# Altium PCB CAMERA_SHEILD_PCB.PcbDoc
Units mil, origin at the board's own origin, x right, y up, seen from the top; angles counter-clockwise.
Board outline 1750 x 2100 mil, 2 copper layers (Top Layer, Bottom Layer); 31 components, 29 nets, 109 pads, 36 vias.
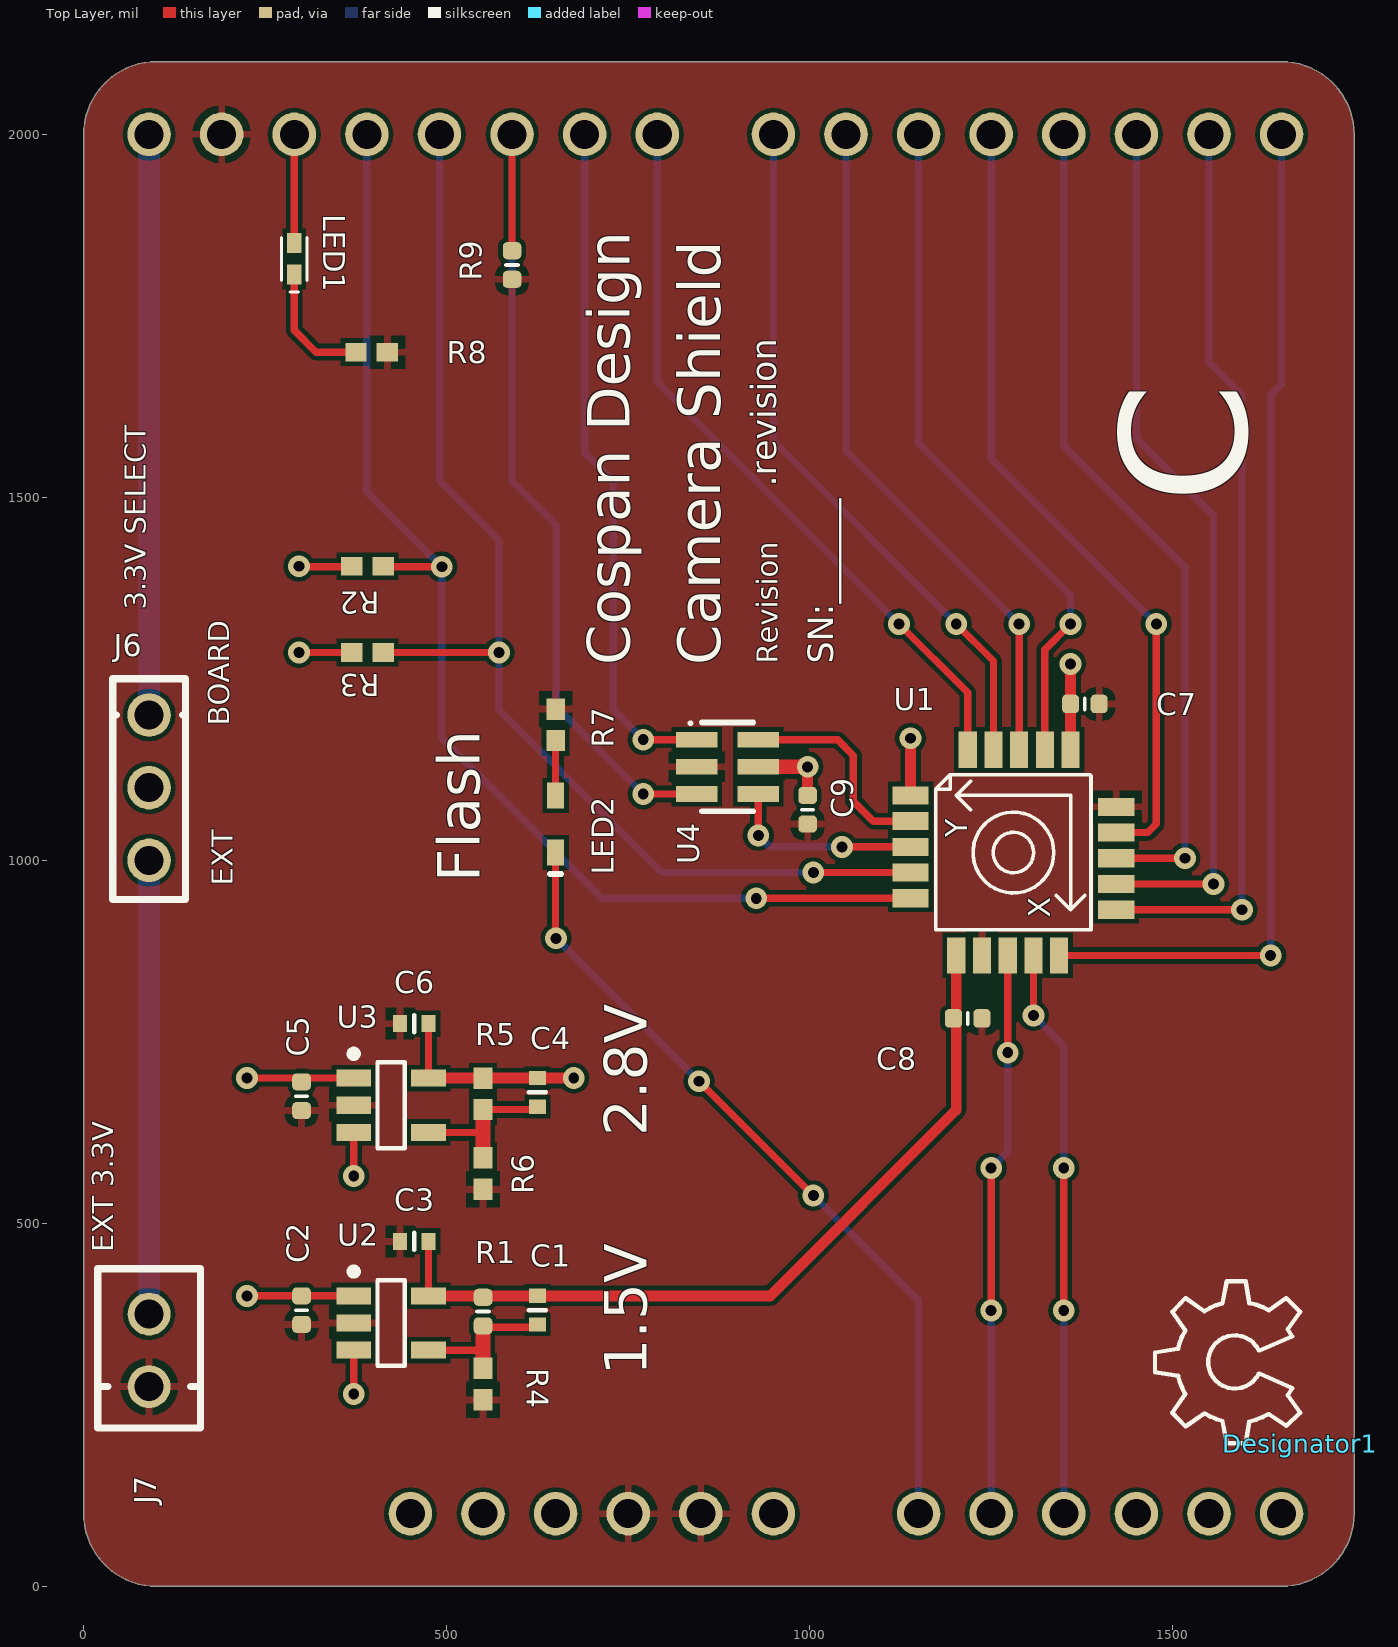
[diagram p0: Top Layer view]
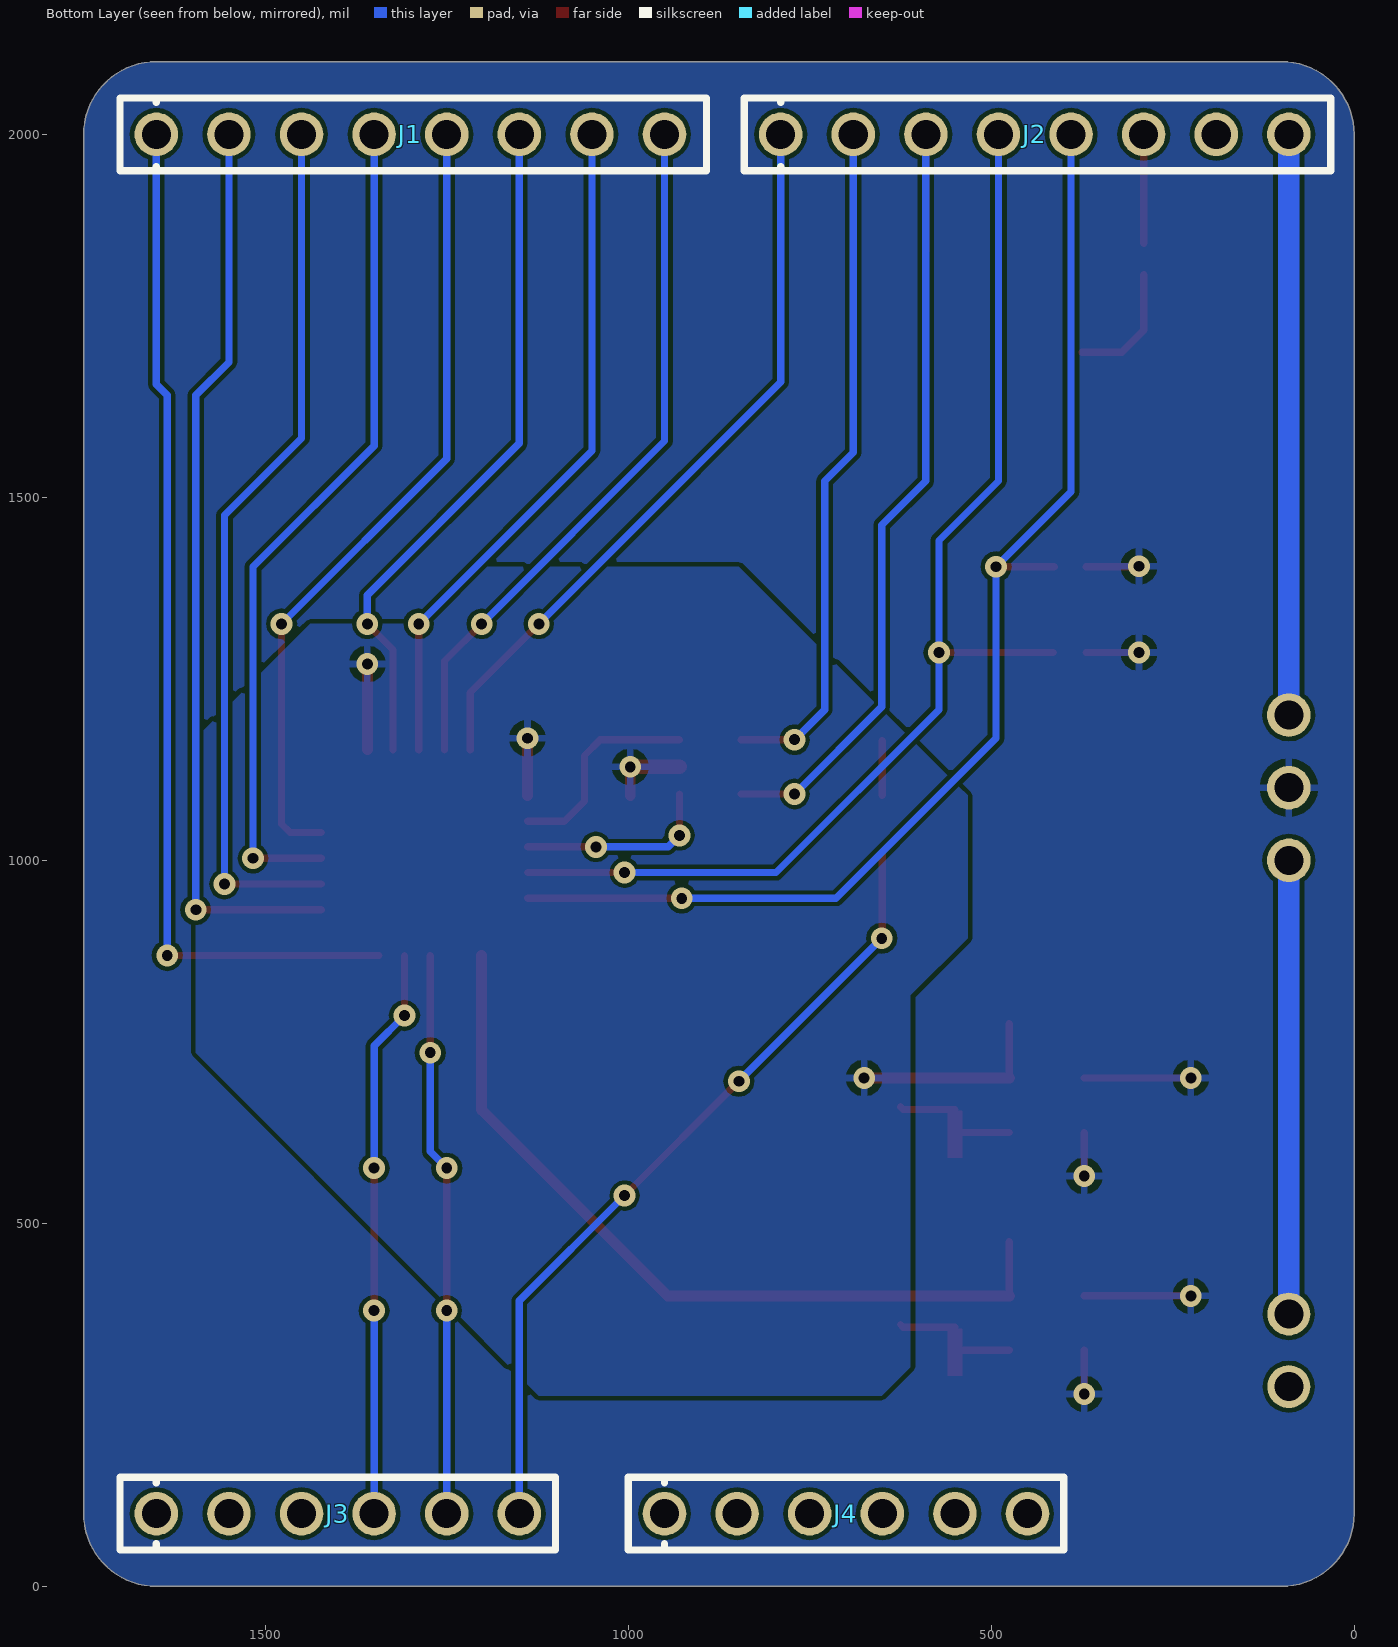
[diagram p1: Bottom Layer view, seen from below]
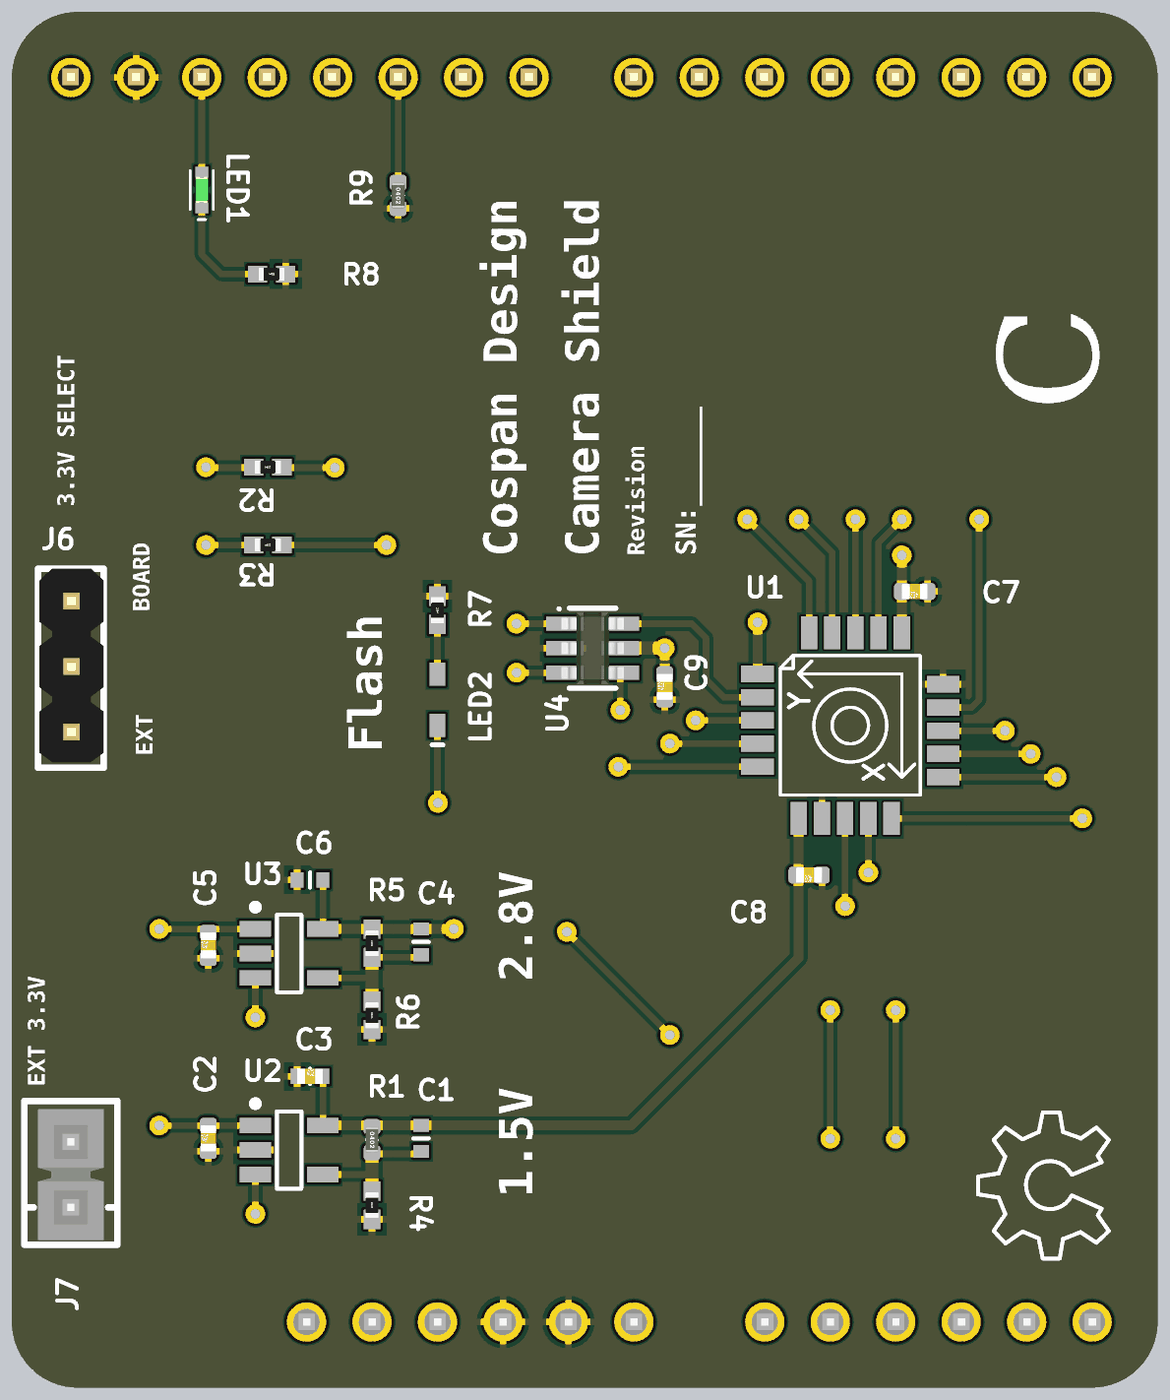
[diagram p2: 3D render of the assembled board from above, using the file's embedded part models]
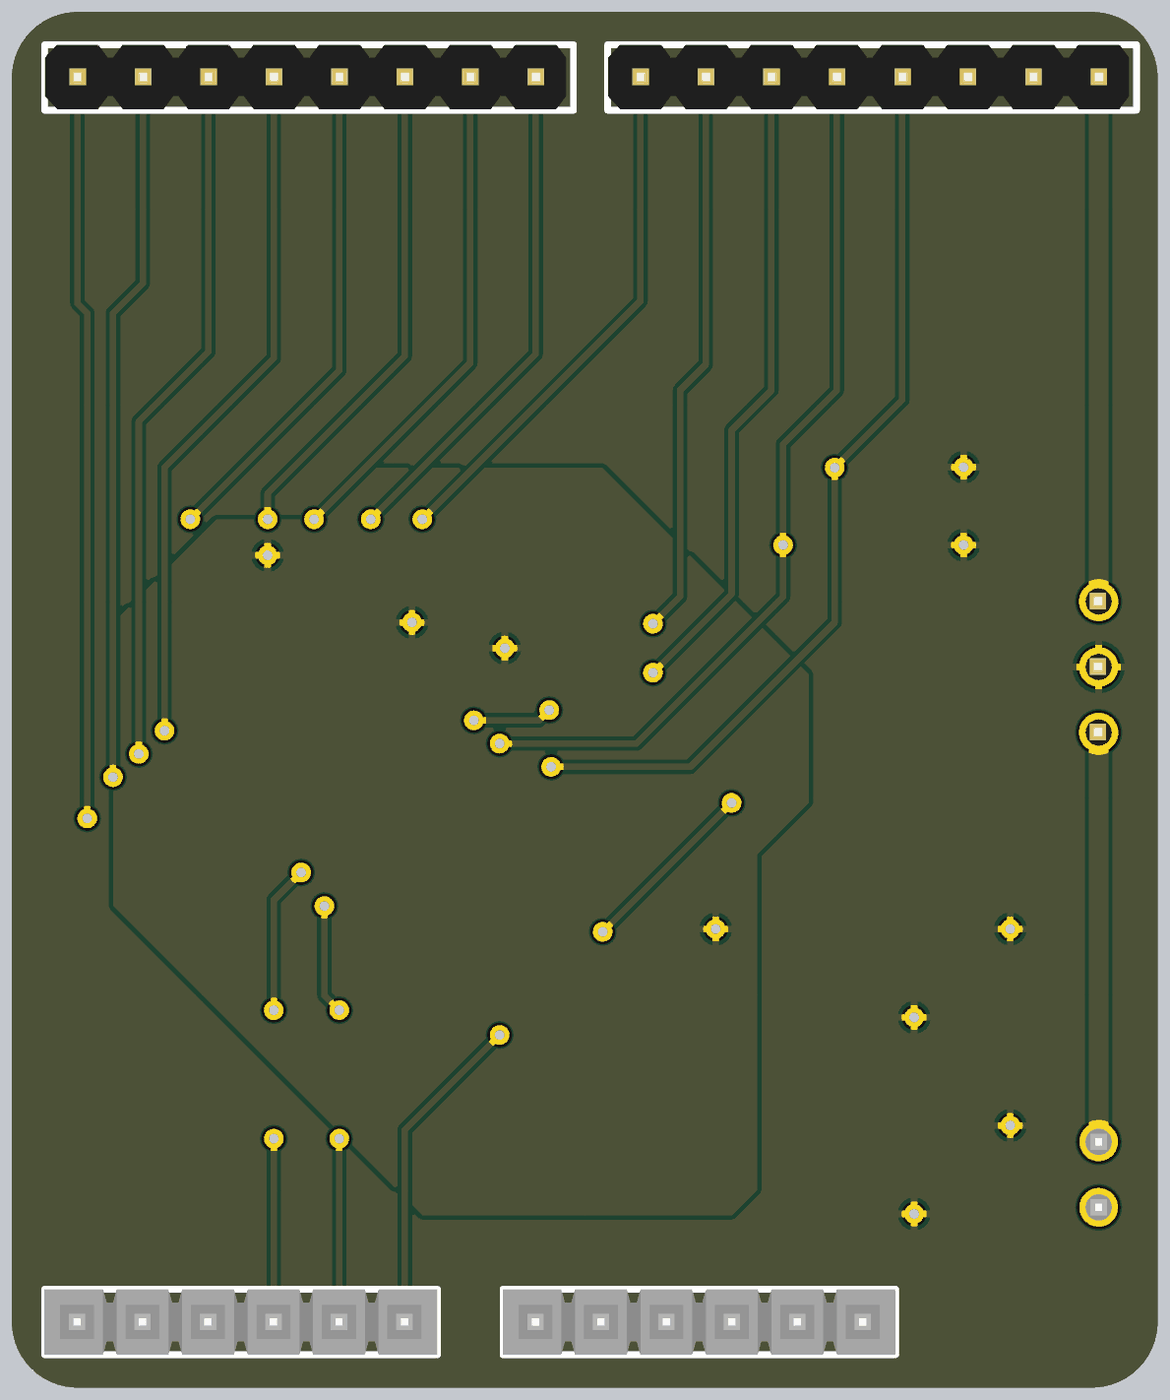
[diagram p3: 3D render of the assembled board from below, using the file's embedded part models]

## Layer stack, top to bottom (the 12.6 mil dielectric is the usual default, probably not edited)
Top Layer: signal copper 1.4
Dielectric: dielectric 12.6, FR-4, Dk 4.8
Bottom Layer: signal copper 1.4

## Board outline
0,100 0,2000 cw(c100,2000) 100,2100 1650,2100 cw(c1650,2000) 1750,2000 1750,100 cw(c1650,100) 1650,0 100,0 cw(c100,100)

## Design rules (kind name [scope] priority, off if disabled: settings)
Clearance [All] p1: gap=6
MinimumSolderMaskSliver [All] p1: minsoldermaskwidth=3
PolygonConnect [All] p1: connectstyle=Relief reliefconductorwidth=10 reliefentries=4 polygonreliefangle="90 Angle" airgapwidth=10
RoutingVias [All] p1: holewidth=15 width=30 viastyle="Through Hole" minholewidth=15 minwidth=30 maxholewidth=28 maxwidth=50
SilkToSilkClearance [All] p1: silktosilkclearance=5
SilkToSolderMaskClearance SilkscreenOverComponentPads [IsPad] p1: minsilkscreentomaskgap=3 clearancetoexposedcopper=TRUE
SolderMaskExpansion [All] p1: expansion=4
Width [All] p1: maxlimit=50 minlimit=6 preferedwidth=6
25 further rules are at their usual default settings.

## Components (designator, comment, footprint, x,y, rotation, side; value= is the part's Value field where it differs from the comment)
C1 "1000pF" C_ERA-0402 625,380.31 r90 top
C2 "0.1uF" C_0402 300,380.31 r90 top
C3 "2.2uF" C_ERA-0402 455.31,475 r0 top
C4 "1000pF" C_ERA-0402 625,680.31 r90 top
C5 "0.1uF" C_0402 300,675 r90 top
C6 "2.2uF" C_ERA-0402 455.31,775 r0 top
C7 "0.1uF" C_0402 1379.06,1215.35 r180 top
C8 "0.1uF" C_0402 1217.64,782.28 r180 top
C9 "0.1uF" C_0402 997.17,1069.69 r90 top
Designator1 "Comment" OSHW_6X200_NOTEXT 1675.59,196.97 r90 top (schematic designator U$5)
J1 "J_HDR1X8_THRHOLE_VERT" HDR_1X8 1650,2000 r180 bottom locked
J2 "J_HDR1X8_THRHOLE_VERT" HDR_1X8 790,2000 r180 bottom locked
J3 "J_HDR1X6_THRHOLE_VERT" HDR_1X6 1650,100 r180 bottom locked
J4 "J_HDR1X6_THRHOLE_VERT" HDR_1X6 950,100 r180 bottom locked
J6 "J_HDR1X3_JUMPER_SELECT" HDR_1X3 90,1200 r270 top
J7 "J_HDR1X2_JUMPER" HDR_1X2 90,275 r90 top
LED1 "LED_GRN_0402" DIOM1005X07L_GREEN 290,1828.35 r90 top
LED2 "LED_WHITE_0603" DIOM0603 650,1050 r270 top
R1 "R_0402_7.87K" R_0402 550,378.35 r270 top
R2 "2.2k Ohms" ERA-0402 390.87,1405.04 r0 top
R3 "2.2k Ohms" ERA-0402 390.87,1286.22 r0 top
R4 "R_0402_10.0K" ERA-0402 550,278.35 r270 top
R5 "R_0402_13.7K" ERA-0402 550,678.35 r270 top
R6 "R_0402_10.0K" ERA-0402 550,568.35 r270 top
R7 "R_0402_22.0" ERA-0402 650,1186.65 r90 top
R8 "1.0k Ohms" ERA-0402 396.65,1700 r0 top
R9 "R_0402_10.0K" R_0402 590,1820 r270 top
U1 "640X480 Camera" TCM8230MD 1280.63,1010.63 r90 top
U2 "VREG" SOT95P280X90-5N 423.43,362.6 r0 top
U3 "VREG" SOT95P280X90-5N 423.43,662.6 r0 top
U4 "2 X BUFFER" SOT23-6 886.93,1128.74 r270 top

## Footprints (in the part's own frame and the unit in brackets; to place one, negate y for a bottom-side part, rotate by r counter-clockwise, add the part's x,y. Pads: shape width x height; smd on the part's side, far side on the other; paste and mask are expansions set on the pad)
C_0402 [mm] "Capacitor 0402"
  rrect50% 0.6x0.65 smd: 1(-0.5,0) 2(0.5,0)
  silkscreen extent 0,-0.2 0,0.2, body extent -0.5,-0.3 0.5,0.3, height 0.2
C_ERA-0402 [mm]
  rect 0.5x0.6 smd: 1(-0.5,0) 2(0.5,0)
  silkscreen extent 0,-0.3 0,0.3, body extent -0.51,-0.3 0.51,0.3, height 0.2
DIOM0603 [mm] "Molded Diode, 2-Leads, Body 1.2x0.8mm, IPC Medium Density"
  rect 0.9x0.6 smd: 1(-1,0) 2(1,0)
  silkscreen extent 1.75,-0.2 1.75,0.2, body extent -0.65,-0.45 0.65,0.45, height 0.7
DIOM1005X07L_GREEN [mm] "Molded Diode, 2-Leads, Body 1.0x0.5mm, IPC High Density"
  rect 0.7x0.5 smd: 1(0.55,0) 2(-0.55,0)
  silkscreen extent -1.15,-0.45 0.75,0.45, body extent -0.5,-0.25 0.51,0.25, height 0.45
ERA-0402 [mm] "Chip Resistor, 2-Leads, Body 1.0x0.5mm, IPC Medium Density"
  rect 0.75x0.65 smd: 1(-0.55,0) 2(0.55,0)
  body extent -0.5,-0.25 0.5,0.25, height 0.33
HDR_1X2 [mm] "Jumper"
  round 1.5 hole 1.016: 1(0,0) 2(2.54,0)
  silkscreen extent -1.45,-1.8 4.13,1.8, body extent -1.27,-1.27 3.81,1.27, height 8.38
HDR_1X3 [mil] "HEADER"
  round 60 hole 40: 1(0,0) 2(100,0) 3(200,0)
  silkscreen extent -50,-50 254,50, body extent -51,-48 245,50, height 329
HDR_1X6 [mil] "HEADER"
  round 60 hole 40: 1(0,0) 2(100,0) 3(200,0) 4(300,0) 5(400,0) 6(500,0)
  silkscreen extent -50,-50 550,50, body extent -50,-50 550,50, height 334
HDR_1X8 [mil] "HEADER"
  round 60 hole 40: 1(0,0) 2(100,0) 3(200,0) 4(300,0) 5(400,0) 6(500,0) 7(600,0) 8(700,0)
  silkscreen extent -50,-50 758,50, body extent -50,-48 746,50, height 329
OSHW_6X200_NOTEXT [mil]
  silkscreen extent 0,0 223,200
R_0402 [mm] "Resistor 0402"
  rrect50% 0.6x0.65 smd: 1(-0.5,0) 2(0.5,0)
  silkscreen extent 0,-0.2 0,0.2, body extent -0.51,-0.25 0.51,0.25, height 0.51
SOT23-6 [mm] "SOT-23/SC-74A; 6 Leads; Body 3 x 3 mm, inc. leads (LxW max)"
  rect 0.55x1.45 smd: 1(-0.95,-1.075) 2(0,-1.075) 3(0.95,-1.075) 4(0.95,1.075) 5(0,1.075) 6(-0.95,1.075)
  silkscreen extent -1.57,-1.35 1.55,0.9, body extent -1.39,-1.2 1.4,1.22, height 1.09
SOT95P280X90-5N [mm] "SOT23, 5-Leads, Body 3.0x2.8mm (max), Pitch 0.95mm, IPC Medium Density"
  rect 1.22x0.6 smd: 1(-1.31,0.95) 2(-1.31,0) 3(-1.31,-0.95) 4(1.31,-0.95) 5(1.31,0.95)
  silkscreen extent -1.43,-1.5 0.48,1.92, body extent -0.87,-1.5 0.87,1.5, height 0.9
TCM8230MD [mm]
  rect 0.635x1.27 smd mask+0.076: 1(2,3.6) 2(1.1,3.6) 3(0.2,3.6) 4(-0.7,3.6) 5(-1.6,3.6) 11(-2,-3.6) 12(-1.1,-3.6) 13(-0.2,-3.6) 14(0.7,-3.6) 15(1.6,-3.6)
  rect 1.27x0.635 smd mask+0.076: 6(-3.6,2) 7(-3.6,1.1) 8(-3.6,0.2) 9(-3.6,-0.7) 10(-3.6,-1.6) 16(3.6,-2) 17(3.6,-1.1) 18(3.6,-0.2) 19(3.6,0.7) 20(3.6,1.6)
  silkscreen extent -2.7,-2.72 2.72,2.72

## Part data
C1 C4: library part C_0402_1000PF_50V, "CAP CER 1000PF 50V C0G 0402"
C2 C5 C7 C8 C9: library part C_0402_0.1UF_16V, "CAP CER .10UF 16V X7R 0402"
C3 C6: library part C_0402_2.2UF, "CAP CER 2.2UF 6.3V X5R 0402"
J1 J2 J3 J4: "CONN HEADER .100\" 12POS TIN PCB"
J6: "CONN HEADER .100\" 3POS TIN PCB"
J7: "CONN HEADER .100\" 2POS TIN PCB"
LED1: "LED 1X0.5MM 570NM GN WTR CLR SMD"
LED2: "LED SMARTLED WHITE DIFF 0603 SMD"
R1: "RES 7.87K OHM 1/16W 1% 0402 SMD"
R2 R3: library part R_0402_2.2K, "RES 2.20K OHM 1/10W 1% 0402 SMD"
R4 R6 R9: "RES 10.0K OHM 1/16W 1% 0402 SMD"
R5: "RES 13.7K OHM 1/10W 1% 0402 SMD"
R7: "RES 22.0 OHM 1/16W 1% 0402 SMD"
R8: library part R_0402_1.0K, "RES 1.00K OHM 1/16W 1% 0402 SMD"
U1: library part U_TCM8230MD_CAMERA, "640 x 480 SPARKFUN CAMERA"
U2 U3: library part U_TPS79901DDCR, "IC REG LDO ADJ .2A TSOT-23-5"
U4: library part U_SN74LVC2G34DBVR, "IC BUFFER DUAL NON-INV SOT23-6"

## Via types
v1: diameter 30, hole 15, Top Layer to Bottom Layer, 36 vias

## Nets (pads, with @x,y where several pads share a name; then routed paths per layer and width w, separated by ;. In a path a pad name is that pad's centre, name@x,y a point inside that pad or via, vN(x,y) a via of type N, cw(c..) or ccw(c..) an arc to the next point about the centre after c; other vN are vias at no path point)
C\A\M\_\R\S\T\_\V\2\P\8\: U1.3 U4.4 | length 273.3
  Top Layer w10: v1(929.25,1034.25) U4.4 ; v1(1044.41,1018.5) U1.3
  Bottom Layer w10: v1(929.25,1034.25) 945,1018.5 v1(1044.41,1018.5)
CAM_CLK_IN: J2.2 U4.1 | length 941.1
  Top Layer w10: v1(770.79,1166.14) U4.1
  Bottom Layer w10: J2.2 690.08,1999.92 690.08,1561.81 729.45,1522.44 729.45,1207.48 v1(770.79,1166.14)
CAM_CLK_IN_V2P8: U1.2 U4.6 | length 293
  Top Layer w10: U4.6 1038.5,1166.14 1060.16,1144.49 1060.16,1081.5 1087.72,1053.94 U1.2
CAM_D0: J1.2 U1.11 | length 1260.2
  Top Layer w10: U1.11 v1(1595.59,931.89)
  Bottom Layer w10: J1.2 1550,1686.14 1595.59,1640.55 v1(1595.59,931.89)
CAM_D1: J1.3 U1.12 | length 1210.5
  Top Layer w10: U1.12 v1(1556.22,967.32)
  Bottom Layer w10: J1.3 1450,1581.42 1556.22,1475.2 v1(1556.22,967.32)
CAM_D2: J1.4 U1.13 | length 1160.8
  Top Layer w10: U1.13 v1(1516.85,1002.76)
  Bottom Layer w10: J1.4 1350,1571.18 1516.85,1404.33 v1(1516.85,1002.76)
CAM_D3: J1.5 U1.14 | length 1104.2
  Top Layer w10: U1.14 1465.67,1038.19 1477.48,1050 v1(1477.48,1325.59)
  Bottom Layer w10: J1.5 1250,1553.07 v1(1477.48,1325.59)
CAM_D4: J1.6 U1.17 | length 949
  Top Layer w10: U1.17 1323.94,1290.16 v1(1359.37,1325.59)
  Bottom Layer w10: J1.6 1150,1574.33 1359.37,1364.96 v1(1359.37,1325.59)
CAM_D5: J1.7 U1.18 | length 946.4
  Top Layer w10: U1.18 v1(1288.5,1325.59)
  Bottom Layer w10: J1.7 1050,1564.09 v1(1288.5,1325.59)
CAM_D6: J1.8 U1.19 | length 973.2
  Top Layer w10: v1(1201.89,1325.59) 1253.07,1274.41 U1.19
  Bottom Layer w10: J1.8 950,1577.48 v1(1201.89,1325.59)
CAM_D7: J2.1 U1.20 | length 1024.8
  Top Layer w10: v1(1123.15,1325.59) 1217.64,1231.1 U1.20
  Bottom Layer w10: J2.1 790,1658.74 v1(1123.15,1325.59)
CAM_HSYNC: J3.4 U1.9 | length 786.2
  Top Layer w10: v1(1308.19,786.22) U1.9 ; v1(1350,379.84) v1(1350,576.06)
  Bottom Layer w10: v1(1308.19,786.22) 1350,744.41 v1(1350,576.06) ; J3.4 v1(1350,379.84)
CAM_PIXCLK: J1.1 U1.10 | length 1428.7
  Top Layer w10: U1.10 v1(1634.96,868.9)
  Bottom Layer w10: v1(1634.96,868.9) 1634.96,1640.55 1650,1655.59 J1.1
CAM_RST: J2.3 R9.1 U4.3 | length 1217.7
  Top Layer w10: R9.1 J2.3 ; v1(770.79,1091.34) U4.3
  Bottom Layer w10: J2.3 590,1522.44 650.71,1461.73 650.71,1211.42 v1(770.79,1091.34)
CAM_VSYNC: J3.5 U1.8 | length 778.3
  Top Layer w10: v1(1250,379.84) v1(1250,576.06) ; v1(1272.76,735.04) U1.8
  Bottom Layer w10: J3.5 v1(1250,379.84) ; v1(1250,576.06) 1272.76,598.82 v1(1272.76,735.04)
CAMERA_FLASH: J3.6 LED2.2 | length 1117.4
  Top Layer w10: v1@650,892.52 LED2.2 ; v1(847.56,695.67) v1(1005.04,538.19)
  Bottom Layer w10: v1(650.71,892.52) v1(847.56,695.67) ; v1(1005.04,538.19) 1150,393.23 J3.6
CAMERA_LED: J2.6 LED1.1 | length 150
  Top Layer w10: LED1.1 J2.6
GND: C2.1 C3.1 C5.1 C6.1 C7.1 C8.1 C9.1 J2.7 J4.2 J4.3 J7.1 R4.2 R6.2 R7.2 R8.2 R9.2 U1.7 U1.15 U2.2 U3.2 U4.2
I2C_SCL: J2.4 R3.2 U1.4 | length 1644
  Top Layer w10: R3.2@414.37,1286.22 v1(571.97,1286.22) ; v1(1005.04,983.07) U1.4
  Bottom Layer w10: J2.4 490,1522.44 571.97,1440.47 571.97,1207.48 796.38,983.07 v1(1005.04,983.07)
I2C_SDA: J2.5 R2.2 U1.5 | length 1692.2
  Top Layer w10: R2.2@412.72,1404.33 v1(493.23,1404.33) ; v1(926.3,947.64) U1.5
  Bottom Layer w10: J2.5 390,1507.56 v1(493.23,1404.33) 493.23,1168.11 713.7,947.64 v1(926.3,947.64)
NetC1_1: C1.1 R1.2 R4.1 U2.4 | length 151.6
  Top Layer w10: U2.4 550,325.2 ; R1.2@550,356.69 621.06,356.69 C1.1
NetC4_1: C4.1 R5.2 R6.1 U3.4 | length 151.6
  Top Layer w10: U3.4 550,625.2 ; R5.2 621.06,656.69 C4.1
NetJ6_3: J6.3 J7.2 | length 625
  Bottom Layer w30: J7.2 J6.3
NetLED1_2: LED1.2 R8.1 | length 174.1
  Top Layer w10: LED1.2 290,1730 320,1700 R8.1
NetLED2_1: LED2.1 R7.1 | length 75.6
  Top Layer w10: LED2.1 R7.1
V1P5: C1.2 C3.2 C8.2 R1.1 U1.6 U2.5 | length 1120.7
  Top Layer w10: U2.5 C3.2
  Top Layer w15: U2.5 945.59,400 1201.89,656.3 U1.6
V2P8: C4.2 C6.2 C7.2 C9.2 R5.1 U1.1 U1.16 U3.5 U4.5 | length 579.1
  Top Layer w10: U3.5 C6.2
  Top Layer w15: U3.5 v1(675,700) ; C9.2 v1(997.17,1128.74) ; U1.1 v1(1138.9,1168.11) ; U1.16 v1(1359.37,1270.47)
  Top Layer w20: U4.5 v1(997.17,1128.74)
V3P3: C2.2 C5.2 J6.2 R2.1 R3.1 U2.1 U2.3 U3.1 U3.3 | length 577.4
  Top Layer w10: v1(225,400) U2.1 ; v1(225,700) U3.1 ; v1(296.38,1286.22) R3.1 ; v1(296.38,1405.04) 288.43,1405.04 287.72,1404.33 R2.1@369.21,1404.33 ; v1(371.85,265) U2.3 ; v1(371.85,565) U3.3
V3P3_DIONYSUS: J2.8 J6.1 | length 800
  Bottom Layer w30: J6.1 J2.8
pads on no net: J3.1 J3.2 J3.3 J4.1 J4.4 J4.5 J4.6

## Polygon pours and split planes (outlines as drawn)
GND on Top Layer "GROUND" (solid, pour order 6): 0,100 0,2000 cw(c100,2000) 100,2100 1650,2100 cw(c1650,2000) 1750,2000 1750,100 cw(c1650,100) 1650,0 100,0 cw(c100,100)
V2P8 on Bottom Layer "V2P8_PLANE" (solid, pour order 5): 611.34,735.04 611.34,813.78 532.6,892.52 532.6,1089.37 847.56,1404.33 1201.89,1404.33 1280.63,1325.59 1438.11,1325.59 1595.59,1168.11 1595.59,735.04 1123.15,262.6 650.71,262.6 611.34,301.97
V3P3 on Bottom Layer "V3P3_PLANE" (solid, pour order 11): 0,100 0,2000 cw(c100,2000) 100,2100 1650,2100 cw(c1650,2000) 1750,2000 1750,100 cw(c1650,100) 1650,0 100,0 cw(c100,100)

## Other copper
Top Layer:
  region net NetC1_1: 540,355 540,290 560,290 560,355
  region net NetC4_1: 540,655 540,590 560,590 560,655

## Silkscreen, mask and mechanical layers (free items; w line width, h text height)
Top Overlay:
  text ".revision" at 965.67,1514.57 h60 r90
  text "C" at 1658.58,1490.94 h300 r90
  text "3.3V SELECT" at 95,1345 h50 r90
  text "Revision" at 965.67,1270.47 h50 r90
  text "SN:______" at 1044.41,1270.47 h60 r90
  text "Cospan Design" at 771.22,1268.39 h100 r90
  text "Camera Shield" at 896.22,1268.39 h100 r90
  text "BOARD" at 210,1185 h50 r90
  text "Flash" at 565,970 h100 r90
  text "EXT" at 215,965 h50 r90
  text "2.8V" at 795.09,620 h100 r90
  text "EXT 3.3V" at 50,460 h50 r90
  text "1.5V" at 795,290 h100 r90
Mechanical 2:
  the board outline again, w6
